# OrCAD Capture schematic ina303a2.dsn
size A; title: INA293 40-V High-Voltage, High Bandwidth, Unidirectional, 110-V Common-Mode Current-Sense Amplifier; rev: A; note: SBOS870
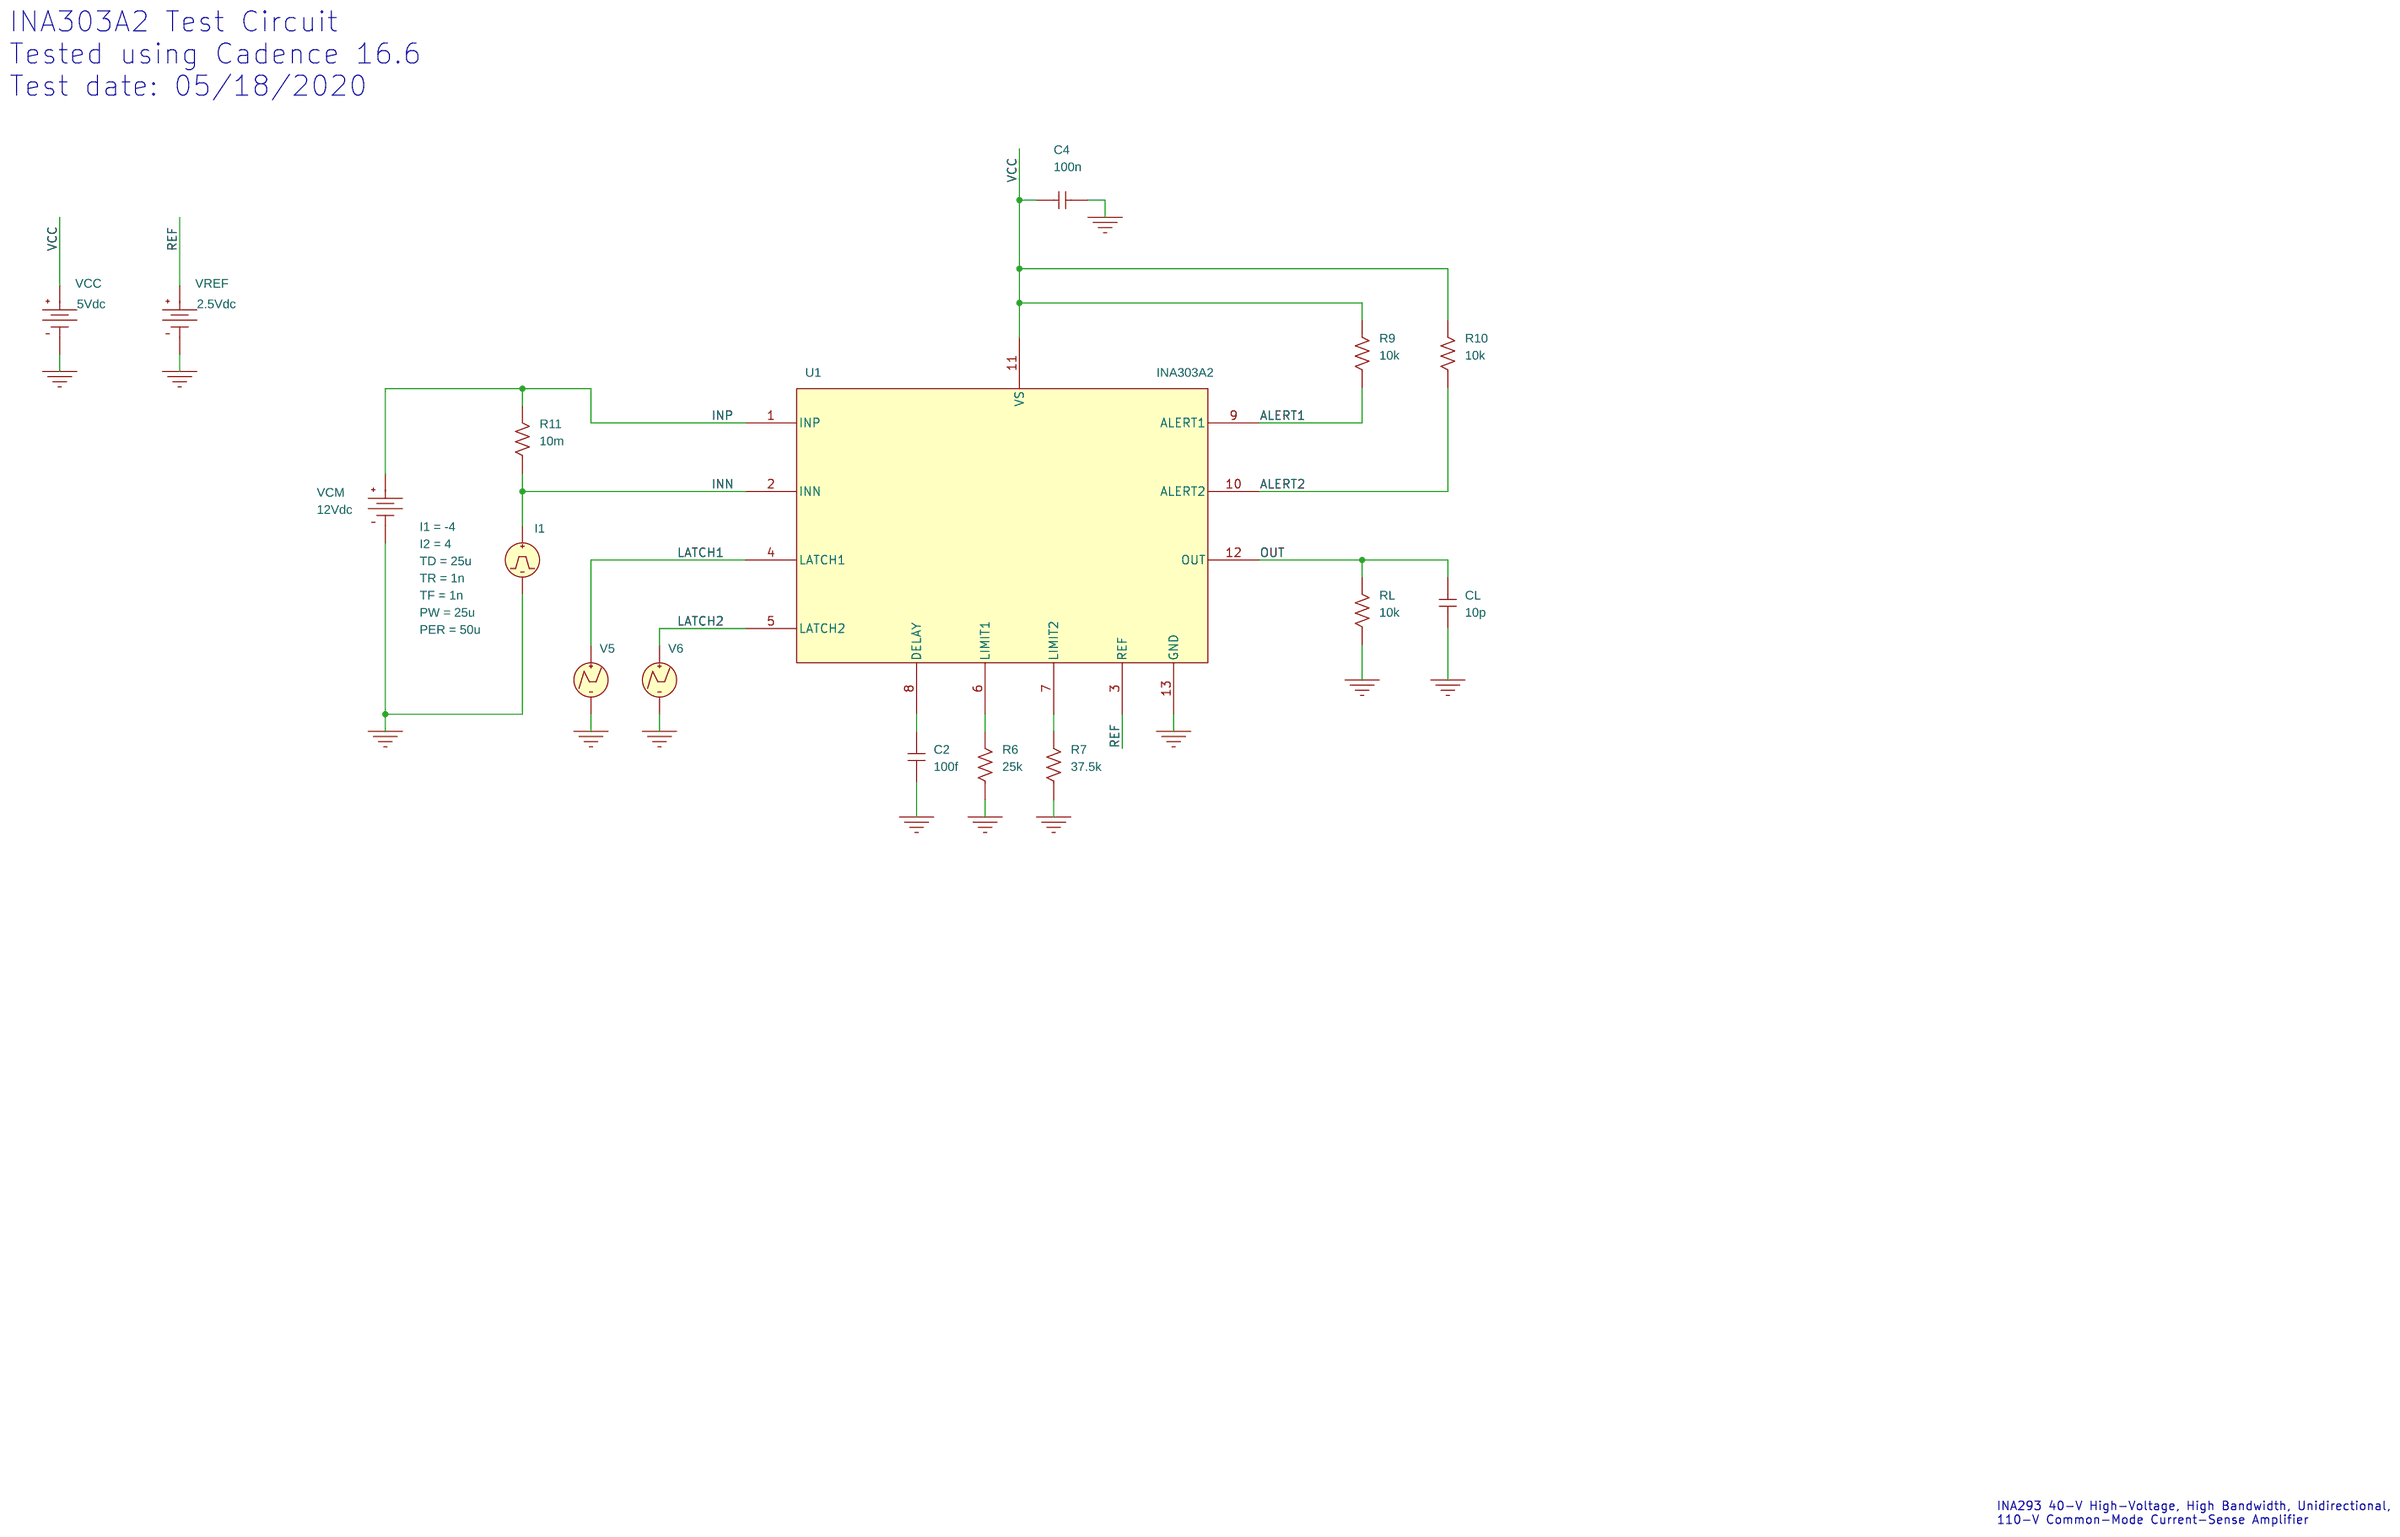
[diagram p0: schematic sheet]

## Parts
C2  100f  [RAD/CK05]
C4  100n  [RAD/CK05]
CL  10p  [RAD/CK05]
I1  IPULSE
R6  25k  [AX/RC05]
R7  37.5k  [AX/RC05]
R9  10k  [AX/RC05]
R10  10k  [AX/RC05]
R11  10m  [AX/RC05]
RL  10k  [AX/RC05]
U1  INA303A2
V5  VPWL
V6  VPWL
VCC  VDC
VCM  VDC
VREF  VDC

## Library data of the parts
C2 C4 CL = C
I1 = IPULSE: I1: -4; I2: 4; PER: 50u; PW: 25u; TD: 25u; TF: 1n; TR: 1n
R6 R7 R9-R11 RL = R
U1 = INA303A2
V5 = VPWL: T1: 0; T2: 5m; T3: 5.000001m; T4: 9.5m; T5: 9.500001m; V1: 0; V2: 0; V3: 5; V4: 5; V5: 0
V6 = VPWL: T1: 0; T2: 13m; T3: 13.000001m; T4: 18.5m; T5: 18.500001m; V1: 0; V2: 0; V3: 5; V4: 5; V5: 0
VCC = VDC: DC: 5Vdc
VCM = VDC: DC: 12Vdc
VREF = VDC: DC: 2.5Vdc

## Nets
VCC: C4.2 R9.2 R10.2 U1.11(VS) VCC.0(+)
0: C2.1 C4.1 CL.1 I1.2(-) R6.1 R7.1 RL.1 U1.13(GND) V5.2(-) V6.2(-) VCC.1(-) VCM.1(-) VREF.1(-)
ALERT1: R9.1 U1.9(ALERT1)
ALERT2: R10.1 U1.10(ALERT2)
INN: I1.1(+) R11.1 U1.2(INN)
INP: R11.2 U1.1(INP) VCM.0(+)
LATCH1: U1.4(LATCH1) V5.1(+)
LATCH2: U1.5(LATCH2) V6.1(+)
OUT: CL.2 RL.2 U1.12(OUT)
REF: U1.3(REF) VREF.0(+)
N22835: C2.2 U1.8(DELAY)
N22917: R7.2 U1.7(LIMIT2)
N22923: R6.2 U1.6(LIMIT1)

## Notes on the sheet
- INA303A2 Test Circuit
  Tested using Cadence 16.6
  Test date: 05/18/2020
- INA293 40-V High-Voltage, High Bandwidth, Unidirectional,
  110-V Common-Mode Current-Sense Amplifier
